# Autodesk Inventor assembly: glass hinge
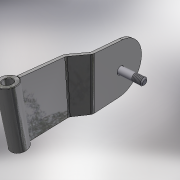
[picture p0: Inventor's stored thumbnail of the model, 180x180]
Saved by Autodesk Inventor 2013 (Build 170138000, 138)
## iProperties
Shininess: 64.0
Length Units: 11269
Angle Units: 11279
Time Units: 11290
Mass Units: 11283
Length Display Precision: 3
Angle Display Precision: 2
Compacted: True
Created: 2004-12
Part Number: glass hinge
Document SubType Name: Assembly
Designer: =<Author>
Manufacturer: Standard
Standards Organization: Custom
Description: =<Part Number>
Mass: 457.379 g
Surface Area: 298.86 cm^2
Volume: 59.0166 cm^3
Density: 7.75 g/cm^3
Density: 0.0
Volumn: 0.0
Area: 0.0
PropertySet Name: Model Information
Control State: 0
Master: False
Checked Out: False
Checked Out Date: 2008-10-15
Last Check In Date: 2008-10-15
Author: PVitaliy
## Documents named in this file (4)
- Y:\Dropbox\Launch 2013\Eco Material Advisor\Assy, Door\_Data\Assy, Cab\glass hinge.iam
- Y:\Dropbox\Launch 2013\Eco Material Advisor\Assy, Door\_Data\Assy, Cab\Hinge 1.ipt
- Y:\Dropbox\Launch 2013\Eco Material Advisor\Assy, Door\_Data\Assy, Cab\List hinge.ipt
- Y:\Dropbox\Launch 2013\Eco Material Advisor\Assy, Door\_Data\Assy, Cab\PK46.51.13.004.ipt
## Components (3 placed, 3 different names)
1. PK46.51.13.004:1 — Insert:1
2. List hinge:1 — Mate:1, Flush:1, Tangent:1, Insert:1
3. Hinge 1:1 — Flush:1, Tangent:1
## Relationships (4: Mate 1, Flush 1, Tangent 1, Insert 1)
- Mate:1: List hinge:1
- Flush:1: List hinge:1 ↔ Hinge 1:1
- Tangent:1: List hinge:1 ↔ Hinge 1:1
- Insert:1: PK46.51.13.004:1 ↔ List hinge:1
